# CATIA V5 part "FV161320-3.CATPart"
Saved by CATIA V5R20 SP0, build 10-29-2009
Part number: FV161320-3
Revision: ANY
Definition: UNKNOWN
Nomenclature: FV161320-3
Source: Unknown
Bounding box of the stored display mesh (mm): x -5.25 to 5.25, y 0 to 5.8, z -5.25 to 5.25
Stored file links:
  C:\Users\Utente\Desktop\IO LAVORO\3D X SITO CF\CUMSA\3D files FV\FV 161320\FV161320-3.CATPart
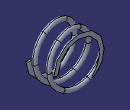
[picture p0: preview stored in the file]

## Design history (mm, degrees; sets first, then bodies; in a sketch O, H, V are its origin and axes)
Body1 "Cortar-Extruir1" (main body)
  Solid1: solid without history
